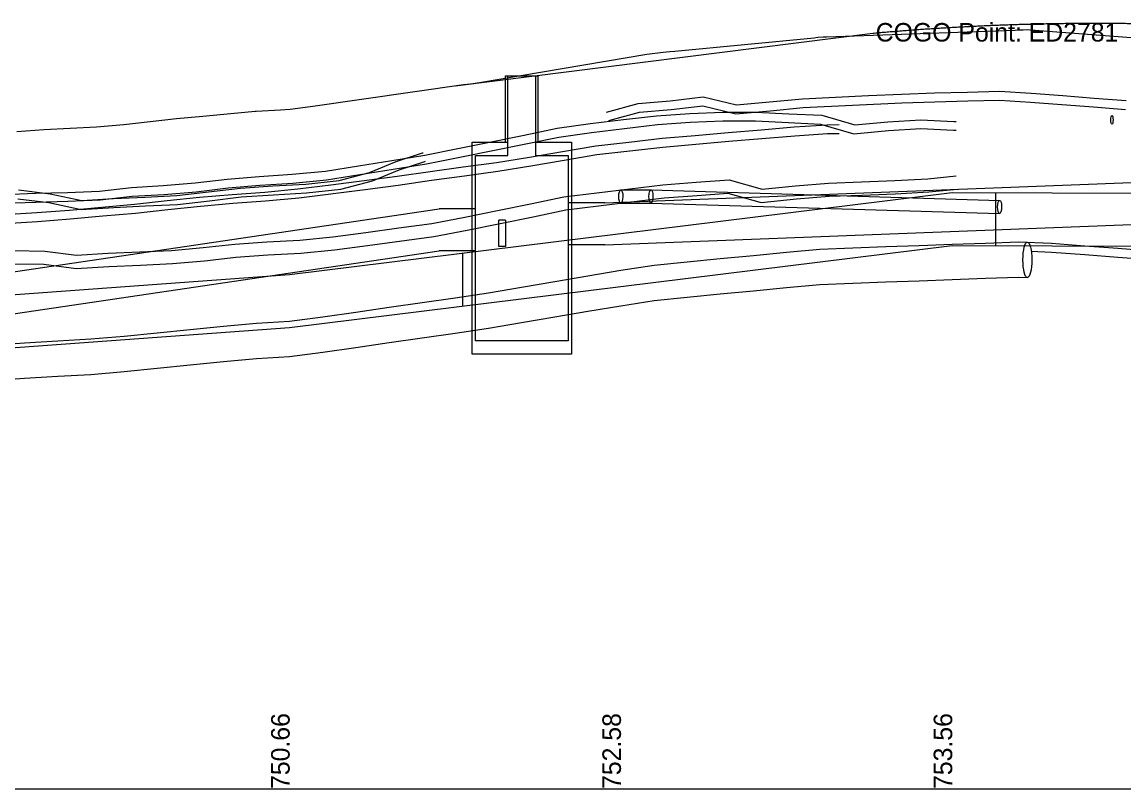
# Model space of a CAD drawing. Extents: x 1833473 to 1837132, y 704683 to 706683.
# Drawn here: x 1833870.4 to 1834036.7, y 705682.6 to 705798.4 of the extents above; entities that cross this region are included whole.
import ezdxf

# ---------------------------------------------------------------- set-up
doc = ezdxf.new("R2010")
doc.units = 0
for name, color, linetype in [('DR_X_Cells', 7, 'Continuous'), ('GK_Cells', 7, 'Continuous'), ('PF_P_Grade_Line', 7, 'Continuous'), ('PF_X_Ground_Line', 7, 'Continuous'), ('PF_X_Text', 7, 'Continuous'), ('SC_Scratch1', 7, 'Continuous'), ('UT_P_Electric', 7, 'Continuous'), ('UT_P_Telecom', 7, 'Continuous'), ('UT_P_Water', 7, 'Continuous'), ('UT_X_Electric', 7, 'Continuous'), ('UT_X_Gas', 7, 'Continuous'), ('UT_X_Telecom', 7, 'Continuous'), ('UT_X_Water', 7, 'Continuous')]:
    doc.layers.add(name, color=color, linetype=linetype)

msp = doc.modelspace()

# ---------------------------------------------------------------- linework, layer by layer
at = {"layer": 'DR_X_Cells'}
for points in [[(1833865.78, 705749.67), (1833870.78, 705750.02), (1833875.78, 705750.33), (1833880.78, 705750.59), (1833885.78, 705751), (1833890.78, 705751.54), (1833895.78, 705752.04), (1833900.78, 705752.51), (1833905.78, 705752.99), (1833910.78, 705753.28), (1833915.78, 705753.93), (1833920.78, 705754.65), (1833925.78, 705755.38), (1833930.78, 705756.1), (1833935.78, 705756.82), (1833940.78, 705757.56), (1833945.78, 705758.41), (1833950.78, 705759.26), (1833955.78, 705760.11), (1833960.78, 705760.96), (1833965.78, 705761.74), (1833970.78, 705762.24), (1833975.78, 705762.72), (1833980.78, 705763.2), (1833985.78, 705763.68), (1833990.78, 705764.16), (1833995.78, 705764.37), (1834000.78, 705764.54), (1834005.78, 705764.72), (1834010.78, 705764.9), (1834015.78, 705765.08), (1834020.78, 705765.28), (1834025.78, 705765.04), (1834030.78, 705764.67), (1834035.78, 705764.29), (1834040.78, 705763.9)], [(1834022.7, 705763.86), (1834025.78, 705763.7), (1834030.78, 705763.33), (1834035.78, 705762.95), (1834040.78, 705762.57)], [(1833865.78, 705744.34), (1833870.78, 705744.69), (1833875.78, 705745), (1833880.78, 705745.25), (1833885.78, 705745.67), (1833890.78, 705746.21), (1833895.78, 705746.71), (1833900.78, 705747.18), (1833905.78, 705747.66), (1833910.78, 705747.95), (1833915.78, 705748.6), (1833920.78, 705749.32), (1833925.78, 705750.04), (1833930.78, 705750.76), (1833935.78, 705751.49), (1833940.78, 705752.22), (1833945.78, 705753.07), (1833950.78, 705753.92), (1833955.78, 705754.77), (1833960.78, 705755.62), (1833965.78, 705756.41), (1833970.78, 705756.91), (1833975.78, 705757.39), (1833980.78, 705757.87), (1833985.78, 705758.35), (1833990.78, 705758.83), (1833995.78, 705759.03), (1834000.78, 705759.21), (1834005.78, 705759.39), (1834010.78, 705759.57), (1834015.78, 705759.75), (1834020.78, 705759.95), (1834022.12, 705759.88)]]:
    msp.add_lwpolyline(points, dxfattribs=at)
msp.add_ellipse((1834022.12, 705762.55), major_axis=(0, 2.67), ratio=0.25, dxfattribs=at)
at = {"layer": 'GK_Cells'}
msp.add_line((1833710.78, 705682.65), (1834910.78, 705682.65), dxfattribs=at)
msp.add_line((1833710.78, 705682.65), (1834910.78, 705682.65), dxfattribs=at)
at = {"layer": 'PF_P_Grade_Line'}
msp.add_line((1833935.78, 705788.82), (1833998.78, 705796.77), dxfattribs=at)
msp.add_spline([(1833998.78, 705796.77), (1833999.74, 705796.85), (1834000.7, 705796.94), (1834001.66, 705797.02), (1834002.62, 705797.09), (1834003.58, 705797.17), (1834004.54, 705797.24), (1834005.5, 705797.31), (1834006.46, 705797.38), (1834007.42, 705797.44), (1834008.38, 705797.51), (1834009.34, 705797.57), (1834010.3, 705797.62), (1834011.26, 705797.68), (1834012.22, 705797.73), (1834013.18, 705797.78), (1834014.14, 705797.83), (1834015.1, 705797.88), (1834016.06, 705797.92), (1834017.02, 705797.96), (1834017.98, 705798), (1834018.94, 705798.03), (1834019.9, 705798.07), (1834020.86, 705798.1), (1834021.82, 705798.13), (1834022.78, 705798.15), (1834023.74, 705798.18), (1834024.7, 705798.2), (1834025.66, 705798.22), (1834026.62, 705798.23), (1834027.58, 705798.25), (1834028.54, 705798.26), (1834029.5, 705798.27), (1834030.46, 705798.27), (1834031.42, 705798.28), (1834032.38, 705798.28), (1834033.34, 705798.28), (1834034.3, 705798.28), (1834035.26, 705798.27), (1834036.22, 705798.26), (1834037.18, 705798.25), (1834038.14, 705798.24), (1834039.1, 705798.22), (1834040.06, 705798.2), (1834041.02, 705798.18), (1834041.98, 705798.16), (1834042.94, 705798.13), (1834043.9, 705798.11), (1834044.86, 705798.08), (1834045.82, 705798.04), (1834046.78, 705798.01)], degree=3, dxfattribs=at)
at = {"layer": 'PF_X_Ground_Line'}
msp.add_lwpolyline([(1833869.59, 705781.93), (1833873.66, 705782.23), (1833881.65, 705782.63), (1833885.73, 705783), (1833893.69, 705783.86), (1833897.67, 705784.21), (1833905.56, 705784.97), (1833905.72, 705784.99), (1833909.42, 705785.2), (1833910.84, 705785.29), (1833914.29, 705785.72), (1833937, 705789), (1833938.09, 705789.12), (1833939.45, 705789.33), (1833964.68, 705793.62), (1833967.14, 705793.89), (1833968.18, 705793.99), (1833968.9, 705794.06), (1833989.92, 705796.08), (1833990.51, 705796.14), (1833991.29, 705796.21), (1833991.78, 705796.22), (1834014.42, 705797.03), (1834020.29, 705797.24), (1834020.64, 705797.27), (1834020.91, 705797.29), (1834021.02, 705797.29), (1834021.16, 705797.28), (1834021.29, 705797.28), (1834021.5, 705797.26), (1834022.14, 705797.3), (1834022.56, 705797.26), (1834023.06, 705797.21), (1834023.12, 705797.22), (1834023.19, 705797.21), (1834023.24, 705797.22), (1834023.29, 705797.22), (1834050.31, 705795.15)], dxfattribs=at)
at = {"layer": 'UT_P_Electric'}
for p, q in [((1833943.37, 705780.3), (1833943.37, 705790.3)), ((1833943.37, 705790.3), (1833948.29, 705790.3)), ((1833943.7, 705778.3), (1833943.7, 705790.3)), ((1833947.95, 705778.3), (1833947.95, 705790.3)), ((1833948.29, 705780.3), (1833948.29, 705790.3)), ((1833938.33, 705748.3), (1833938.33, 705780.3)), ((1833938.33, 705780.3), (1833943.7, 705780.3)), ((1833947.95, 705780.3), (1833953.33, 705780.3)), ((1833953.33, 705780.3), (1833953.33, 705748.3)), ((1833938.83, 705750.3), (1833938.83, 705778.3)), ((1833938.83, 705778.3), (1833943.7, 705778.3)), ((1833947.95, 705778.3), (1833952.83, 705778.3)), ((1833952.83, 705778.3), (1833952.83, 705750.3)), ((1833958.33, 705771.16), (1834139.95, 705778.12)), ((1833958.33, 705764.83), (1834139.95, 705771.79)), ((1833774.58, 705746.77), (1833933.33, 705770.22)), ((1833938.83, 705770.22), (1833933.33, 705770.22)), ((1833958.33, 705771.16), (1833952.83, 705771.16)), ((1833942.34, 705764.55), (1833942.34, 705768.55)), ((1833943.34, 705768.55), (1833942.34, 705768.55)), ((1833943.34, 705768.55), (1833943.34, 705764.55)), ((1833774.58, 705740.44), (1833933.33, 705763.89)), ((1833938.83, 705763.89), (1833933.33, 705763.89)), ((1833943.34, 705764.55), (1833942.34, 705764.55)), ((1833958.33, 705764.83), (1833952.83, 705764.83)), ((1833952.83, 705750.3), (1833938.83, 705750.3)), ((1833953.33, 705748.3), (1833938.33, 705748.3))]:
    msp.add_line(p, q, dxfattribs=at)
at = {"layer": 'UT_P_Telecom'}
for p, q in [((1834017.29, 705772.67), (1834017.29, 705764.65)), ((1833936.86, 705763.56), (1833936.86, 705755.56))]:
    msp.add_line(p, q, dxfattribs=at)
for points in [[(1833910.78, 705760.34), (1834010.78, 705772.69), (1834131.47, 705772.3)], [(1833910.78, 705752.34), (1834010.78, 705764.69), (1834131.47, 705764.3)], [(1833710.78, 705746.64), (1833810.78, 705753.01), (1833910.78, 705760.34)], [(1833710.78, 705738.64), (1833810.78, 705745.01), (1833910.78, 705752.34)]]:
    msp.add_lwpolyline(points, dxfattribs=at)
at = {"layer": 'UT_P_Water'}
for p, q in [((1833960.78, 705773.1), (1833965.33, 705773.1)), ((1833965.33, 705773.1), (1834017.95, 705771.52)), ((1833960.78, 705771.1), (1833965.33, 705771.1)), ((1833965.27, 705771.1), (1834017.95, 705769.52))]:
    msp.add_line(p, q, dxfattribs=at)
for centre in [(1833960.76, 705772.1), (1833965.31, 705772.1), (1834017.93, 705770.52)]:
    msp.add_ellipse(centre, major_axis=(0.01, 1), ratio=0.305644, dxfattribs=at)
at = {"layer": 'UT_X_Electric'}
for points in [[(1833958.59, 705784.85), (1833963.36, 705786.14), (1833968.21, 705786.55), (1833973.21, 705787.15), (1833978.2, 705785.94), (1833983.19, 705786.39), (1833988.17, 705786.86), (1833993.16, 705787.1), (1833998.14, 705787.34), (1834003.13, 705787.58), (1834008.11, 705787.75), (1834013.1, 705787.87), (1834017.92, 705787.99), (1834022.68, 705787.69), (1834027.45, 705787.33), (1834032.22, 705786.96), (1834037.01, 705786.59)], [(1833958.93, 705783.57), (1833963.59, 705784.82), (1833968.35, 705785.22), (1833973.13, 705785.8), (1833978.1, 705784.6), (1833983.31, 705785.06), (1833988.27, 705785.53), (1834003.18, 705786.25), (1834008.15, 705786.41), (1834013.13, 705786.54), (1834017.9, 705786.65), (1834022.59, 705786.36), (1834027.34, 705786), (1834032.12, 705785.63), (1834036.91, 705785.26)], [(1833869.86, 705773.09), (1833874.63, 705772.5), (1833879.41, 705771.5), (1833884.19, 705771.78), (1833888.98, 705772.02), (1833893.76, 705772.25), (1833898.55, 705772.8), (1833903.34, 705773.38), (1833908.24, 705773.7), (1833913.24, 705773.97), (1833918.24, 705774.5), (1833922.84, 705775.72), (1833926.84, 705777.4), (1833930.83, 705778.68), (1833930.95, 705778.71)], [(1833869.76, 705771.76), (1833874.42, 705771.18), (1833879.31, 705770.16), (1833884.26, 705770.45), (1833889.04, 705770.68), (1833893.87, 705770.92), (1833898.7, 705771.47), (1833903.46, 705772.05), (1833908.32, 705772.37), (1833913.34, 705772.64), (1833918.48, 705773.19), (1833923.27, 705774.45), (1833927.3, 705776.14), (1833931.19, 705777.4), (1833931.26, 705777.42)]]:
    msp.add_lwpolyline(points, dxfattribs=at)
msp.add_ellipse((1834034.89, 705783.67), major_axis=(0, -0.667), ratio=0.250004, dxfattribs=at)
at = {"layer": 'UT_X_Gas'}
for points in [[(1833867.62, 705772.42), (1833872.44, 705772.59), (1833877.26, 705772.73), (1833882.08, 705772.91), (1833886.9, 705773.48), (1833891.71, 705773.76), (1833896.52, 705774.15), (1833901.34, 705774.73), (1833906.18, 705775.14), (1833911.18, 705775.46), (1833916.18, 705775.93), (1833921.18, 705776.74), (1833926.18, 705777.54), (1833931.18, 705778.35), (1833936.17, 705779.33), (1833941.17, 705780.37), (1833946.17, 705781.38), (1833951.17, 705782.4), (1833956.17, 705783.12), (1833961.17, 705783.71), (1833966.17, 705784.3), (1833971.17, 705784.66), (1833976.15, 705784.84), (1833981.13, 705784.84), (1833986.12, 705784.6), (1833991.1, 705784.38), (1833996.08, 705782.91), (1834001.07, 705783.39), (1834006.05, 705783.7), (1834011.03, 705783.44), (1834011.36, 705783.44)], [(1833867.68, 705771.09), (1833872.48, 705771.26), (1833877.31, 705771.4), (1833882.18, 705771.58), (1833887.01, 705772.15), (1833891.8, 705772.43), (1833896.66, 705772.82), (1833901.48, 705773.4), (1833906.28, 705773.81), (1833911.28, 705774.13), (1833916.35, 705774.61), (1833931.41, 705777.04), (1833936.44, 705778.02), (1833941.44, 705779.06), (1833951.4, 705781.08), (1833956.34, 705781.79), (1833966.3, 705782.97), (1833971.24, 705783.33), (1833976.17, 705783.51), (1833981.1, 705783.51), (1833986.06, 705783.27), (1833990.88, 705783.05), (1833995.95, 705781.56), (1834001.17, 705782.06), (1834006.06, 705782.37), (1834010.99, 705782.11), (1834011.36, 705782.11)]]:
    msp.add_lwpolyline(points, dxfattribs=at)
at = {"layer": 'UT_X_Telecom'}
for points in [[(1833867.72, 705769.37), (1833872.63, 705769.67), (1833877.54, 705770.05), (1833882.45, 705770.49), (1833887.36, 705770.94), (1833892.27, 705771.48), (1833897.17, 705771.98), (1833902.08, 705772.41), (1833907.01, 705772.78), (1833912.01, 705773.24), (1833917, 705773.87), (1833922, 705774.5), (1833926.99, 705775.16), (1833931.99, 705775.89), (1833936.98, 705776.57), (1833941.98, 705777.24), (1833946.98, 705778.05), (1833951.98, 705778.91), (1833956.98, 705779.75), (1833961.98, 705780.32), (1833966.98, 705780.89), (1833971.97, 705781.34), (1833976.95, 705781.77), (1833981.94, 705782.19), (1833986.92, 705782.61), (1833991.91, 705782.95), (1833993.71, 705782.97)], [(1833867.8, 705768.04), (1833872.72, 705768.34), (1833877.65, 705768.72), (1833882.57, 705769.17), (1833887.5, 705769.61), (1833892.41, 705770.16), (1833897.3, 705770.65), (1833902.19, 705771.09), (1833907.12, 705771.45), (1833912.15, 705771.91), (1833922.17, 705773.17), (1833927.18, 705773.84), (1833932.17, 705774.57), (1833937.16, 705775.25), (1833942.18, 705775.92), (1833947.2, 705776.74), (1833952.2, 705777.6), (1833957.16, 705778.43), (1833962.13, 705779), (1833967.11, 705779.57), (1833972.08, 705780.01), (1833977.06, 705780.44), (1833982.05, 705780.86), (1833987.02, 705781.28), (1833991.96, 705781.62), (1833993.73, 705781.64)]]:
    msp.add_lwpolyline(points, dxfattribs=at)
at = {"layer": 'UT_X_Water'}
for points in [[(1833869.04, 705763.93), (1833873.82, 705763.87), (1833878.6, 705763.23), (1833883.39, 705763.55), (1833888.17, 705763.75), (1833892.96, 705763.97), (1833897.73, 705764.39), (1833902.5, 705764.93), (1833907.35, 705765.27), (1833912.33, 705765.53), (1833917.3, 705766.03), (1833922.27, 705766.67), (1833927.25, 705767.36), (1833932.22, 705768.04), (1833937.2, 705768.98), (1833942.17, 705769.98), (1833947.14, 705770.98), (1833952.14, 705772.05), (1833957.13, 705772.68), (1833962.13, 705773.28), (1833967.12, 705773.88), (1833972.12, 705774.26), (1833977.12, 705774.63), (1833982.11, 705773.23), (1833987.11, 705773.74), (1833992.1, 705774.12), (1833997.1, 705774.31), (1834002.1, 705774.52), (1834007.09, 705774.78), (1834011.36, 705775.21)], [(1833869.09, 705761.93), (1833873.68, 705761.87), (1833878.54, 705761.22), (1833883.49, 705761.55), (1833888.26, 705761.75), (1833893.1, 705761.97), (1833897.93, 705762.4), (1833902.68, 705762.94), (1833907.47, 705763.28), (1833912.48, 705763.54), (1833917.53, 705764.04), (1833922.54, 705764.69), (1833932.54, 705766.07), (1833937.58, 705767.01), (1833942.56, 705768.01), (1833947.55, 705769.02), (1833952.47, 705770.07), (1833957.38, 705770.69), (1833967.32, 705771.89), (1833972.27, 705772.26), (1833976.91, 705772.61), (1833981.94, 705771.2), (1833987.29, 705771.75), (1833992.22, 705772.13), (1833997.18, 705772.31), (1834002.19, 705772.52), (1834007.25, 705772.79), (1834011.56, 705773.22)]]:
    msp.add_lwpolyline(points, dxfattribs=at)

# ---------------------------------------------------------------- texts
at = {"layer": 'PF_X_Text'}
for s, p in [('750.66', (1833910.78, 705682.65)), ('752.58', (1833960.78, 705682.65)), ('753.56', (1834010.78, 705682.65))]:
    msp.add_text(s, height=2.8, rotation=90, dxfattribs=at).set_placement(p)
at = {"layer": 'SC_Scratch1'}
msp.add_text('COGO Point: ED2781', height=2.8, dxfattribs=at).set_placement((1833999.23, 705795.5))

doc.saveas('drawing.dxf')
